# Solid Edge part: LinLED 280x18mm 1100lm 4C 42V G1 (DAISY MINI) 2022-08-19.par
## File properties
Author: mariusz.zatorski
Template: iso metric part.par
Last saved by: mariusz.zatorski
Revision: 1
Application: Solid Edge
Gęstość: 0.000 kg/m^3
Dokładność: 0.990
Username: mariusz.zatorski
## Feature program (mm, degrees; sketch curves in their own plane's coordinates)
body "unnamed Body 1"
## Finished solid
Body 1: solid body, 901 faces, 2350 edges, 1494 vertices.
  Faces by surface: plane 678, cylinder 147, torus 28, spline 24, cone 20, sphere 4
  Edges by curve: line 1828, circle 266, curve on surface 212, spline 44
Bounding box of the edges (mm; curved faces can reach further): 279.600 x 4.050 x 18.000, from (-72.1994, -4.05, -41.6327) to (207.4006, 0, -23.6327).
Cylindrical faces by radius (mm): R0.1 x16, R0.102 x8, R0.25 x8, R0.35 x16, R0.352 x8, R0.5 x12, R0.55 x8, R0.8 x8, R0.9 x4, R1.047 x4, R1.05 x1, R1.1 x4, R1.1249 x4, R1.15 x4, R1.1515 x4, R1.2389 x4, R1.25 x8, R2 x6, R2.1734 x8, R2.5 x4, R5.6968 x4, R5.9345 x4
Conical faces (half-angle, radius in mm at the cone's reference point): 0.1529 deg R0.8961 x4, 4.0564 deg R1.1559 x4, 10.9476 deg R0.928 x4, 39.99 deg R0.9633 x4, 62.9949 deg R0.3743 x4
Toroidal faces (ring radius, tube radius in mm): R-0.3126 r0.9167 x4, R0.55 r0.6 x4, R1.1761 r0.5 x4, R1.1777 r0.5 x4, R1.3 r0.5 x4, R1.4161 r0.5 x8
Spherical faces by radius (mm): R1.1446 x4
Planar faces by outward normal: +x 97, +y 17, +z 109, -x 97, -y 105, -z 109, oblique 144
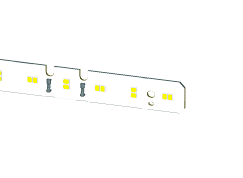
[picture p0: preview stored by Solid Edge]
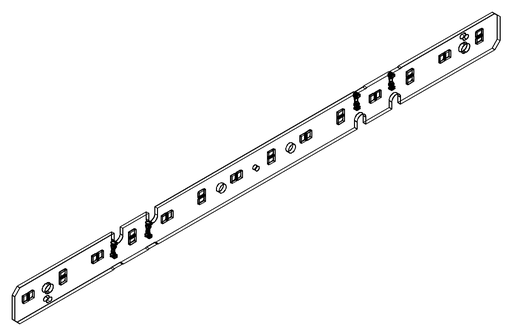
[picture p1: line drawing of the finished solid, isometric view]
